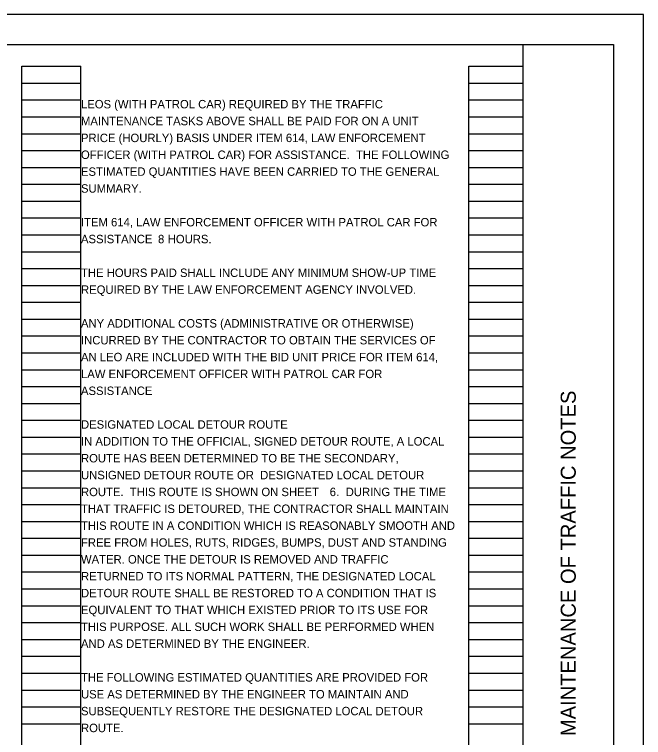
# Model space of a CAD drawing. Extents: x -8.6 to 34, y 0 to 22.
# Drawn here: x 23.56 to 34, y 9.99 to 22 of the extents above; entities that cross this region are included whole.
import ezdxf

# ---------------------------------------------------------------- set-up
doc = ezdxf.new("R2010")
doc.units = 0
for name, color, linetype in [('SC_Scratch1', 7, 'Continuous'), ('SH_Border', 7, 'Continuous'), ('SH_Cut_Line', 7, 'Continuous'), ('SH_Data', 7, 'Continuous'), ('SH_Text', 7, 'Continuous')]:
    doc.layers.add(name, color=color, linetype=linetype)

msp = doc.modelspace()

# ---------------------------------------------------------------- linework, layer by layer
at = {"layer": 'SC_Scratch1'}
for p, q in [((23.68, 0.98), (23.68, 21.14)), ((23.68, 21.14), (24.66, 21.14)), ((24.66, 0.98), (24.66, 21.14)), ((31.1, 0.98), (31.1, 21.14)), ((31.1, 21.14), (32, 21.14)), ((32, 0.98), (32, 21.14)), ((23.68, 20.86), (24.66, 20.86)), ((31.1, 20.86), (32, 20.86)), ((23.68, 20.58), (24.66, 20.58)), ((31.1, 20.58), (32, 20.58)), ((23.68, 20.3), (24.66, 20.3)), ((31.1, 20.3), (32, 20.3)), ((23.68, 20.02), (24.66, 20.02)), ((31.1, 20.02), (32, 20.02)), ((23.68, 19.74), (24.66, 19.74)), ((31.1, 19.74), (32, 19.74)), ((23.68, 19.46), (24.66, 19.46)), ((31.1, 19.46), (32, 19.46)), ((23.68, 19.18), (24.66, 19.18)), ((31.1, 19.18), (32, 19.18)), ((23.68, 18.9), (24.66, 18.9)), ((31.1, 18.9), (32, 18.9)), ((23.68, 18.62), (24.66, 18.62)), ((31.1, 18.62), (32, 18.62)), ((23.68, 18.34), (24.66, 18.34)), ((31.1, 18.34), (32, 18.34)), ((23.68, 18.06), (24.66, 18.06)), ((31.1, 18.06), (32, 18.06)), ((23.68, 17.78), (24.66, 17.78)), ((31.1, 17.78), (32, 17.78)), ((23.68, 17.5), (24.66, 17.5)), ((31.1, 17.5), (32, 17.5)), ((23.68, 17.22), (24.66, 17.22)), ((31.1, 17.22), (32, 17.22)), ((23.68, 16.94), (24.66, 16.94)), ((31.1, 16.94), (32, 16.94)), ((23.68, 16.66), (24.66, 16.66)), ((31.1, 16.66), (32, 16.66)), ((23.68, 16.38), (24.66, 16.38)), ((31.1, 16.38), (32, 16.38)), ((23.68, 16.1), (24.66, 16.1)), ((31.1, 16.1), (32, 16.1)), ((23.68, 15.82), (24.66, 15.82)), ((31.1, 15.82), (32, 15.82)), ((23.68, 15.54), (24.66, 15.54)), ((31.1, 15.54), (32, 15.54)), ((23.68, 15.26), (24.66, 15.26)), ((31.1, 15.26), (32, 15.26)), ((23.68, 14.98), (24.66, 14.98)), ((31.1, 14.98), (32, 14.98)), ((23.68, 14.7), (24.66, 14.7)), ((31.1, 14.7), (32, 14.7)), ((23.68, 14.42), (24.66, 14.42)), ((31.1, 14.42), (32, 14.42)), ((23.68, 14.14), (24.66, 14.14)), ((31.1, 14.14), (32, 14.14)), ((23.68, 13.86), (24.66, 13.86)), ((31.1, 13.86), (32, 13.86)), ((23.68, 13.58), (24.66, 13.58)), ((31.1, 13.58), (32, 13.58)), ((23.68, 13.3), (24.66, 13.3)), ((31.1, 13.3), (32, 13.3)), ((23.68, 13.02), (24.66, 13.02)), ((31.1, 13.02), (32, 13.02)), ((23.68, 12.74), (24.66, 12.74)), ((31.1, 12.74), (32, 12.74)), ((23.68, 12.46), (24.66, 12.46)), ((31.1, 12.46), (32, 12.46)), ((23.68, 12.18), (24.66, 12.18)), ((31.1, 12.18), (32, 12.18)), ((23.68, 11.9), (24.66, 11.9)), ((31.1, 11.9), (32, 11.9)), ((23.68, 11.62), (24.66, 11.62)), ((31.1, 11.62), (32, 11.62)), ((23.68, 11.34), (24.66, 11.34)), ((31.1, 11.34), (32, 11.34)), ((23.68, 11.06), (24.66, 11.06)), ((31.1, 11.06), (32, 11.06)), ((23.68, 10.78), (24.66, 10.78)), ((31.1, 10.78), (32, 10.78)), ((23.68, 10.5), (24.66, 10.5)), ((31.1, 10.5), (32, 10.5)), ((23.68, 10.22), (24.66, 10.22)), ((31.1, 10.22), (32, 10.22))]:
    msp.add_line(p, q, dxfattribs=at)
at = {"layer": 'SH_Border'}
msp.add_line((32, 0.5), (32, 21.5), dxfattribs=at)
msp.add_lwpolyline([(1.5, 21.5), (33.5, 21.5), (33.5, 0.5), (1.5, 0.5)], close=True, dxfattribs=at)
at = {"layer": 'SH_Cut_Line'}
msp.add_lwpolyline([(0, 0), (34, 0), (34, 22), (0, 22)], close=True, dxfattribs=at)

# ---------------------------------------------------------------- texts
at = {"layer": 'SH_Data'}
msp.add_text('MAINTENANCE OF TRAFFIC NOTES', height=0.25, rotation=90, dxfattribs=at).set_placement((32.875, 10.014))
at = {"layer": 'SH_Text'}
for s, p in [('LEOS (WITH PATROL CAR) REQUIRED BY THE TRAFFIC ', (24.66, 20.44)), ('MAINTENANCE TASKS ABOVE SHALL BE PAID FOR ON A UNIT ', (24.66, 20.16)), ('PRICE (HOURLY) BASIS UNDER ITEM 614, LAW ENFORCEMENT ', (24.66, 19.88)), ('OFFICER (WITH PATROL CAR) FOR ASSISTANCE.  THE FOLLOWING ', (24.66, 19.6)), ('ESTIMATED QUANTITIES HAVE BEEN CARRIED TO THE GENERAL ', (24.66, 19.32)), ('SUMMARY.', (24.66, 19.04)), ('ITEM 614, LAW ENFORCEMENT OFFICER WITH PATROL CAR FOR ', (24.66, 18.48)), ('ASSISTANCE ', (24.66, 18.2)), ('8', (25.939, 18.2)), (' HOURS.', (26.048, 18.2)), ('THE HOURS PAID SHALL INCLUDE ANY MINIMUM SHOW-UP TIME ', (24.66, 17.64)), ('REQUIRED BY THE LAW ENFORCEMENT AGENCY INVOLVED.', (24.66, 17.36)), ('ANY ADDITIONAL COSTS (ADMINISTRATIVE OR OTHERWISE) ', (24.66, 16.8)), ('INCURRED BY THE CONTRACTOR TO OBTAIN THE SERVICES OF ', (24.66, 16.52)), ('AN LEO ARE INCLUDED WITH THE BID UNIT PRICE FOR ITEM 614, ', (24.66, 16.24)), ('LAW ENFORCEMENT OFFICER WITH PATROL CAR FOR ', (24.66, 15.96)), ('ASSISTANCE', (24.66, 15.68)), ('DESIGNATED LOCAL DETOUR ROUTE', (24.66, 15.12)), ('IN ADDITION TO THE OFFICIAL, SIGNED DETOUR ROUTE, A LOCAL ', (24.66, 14.84)), ('ROUTE HAS BEEN DETERMINED TO BE THE SECONDARY, ', (24.66, 14.56)), ('UNSIGNED DETOUR ROUTE OR  DESIGNATED LOCAL DETOUR ', (24.66, 14.28)), ('ROUTE.  THIS ROUTE IS SHOWN ON SHEET ', (24.66, 14)), ('6', (28.79, 14)), ('.  DURING THE TIME ', (28.899, 14)), ('THAT TRAFFIC IS DETOURED, THE CONTRACTOR SHALL MAINTAIN ', (24.66, 13.72)), ('THIS ROUTE IN A CONDITION WHICH IS REASONABLY SMOOTH AND ', (24.66, 13.44)), ('FREE FROM HOLES, RUTS, RIDGES, BUMPS, DUST AND STANDING ', (24.66, 13.16)), ('WATER. ONCE THE DETOUR IS REMOVED AND TRAFFIC ', (24.66, 12.88)), ('RETURNED TO ITS NORMAL PATTERN, THE DESIGNATED LOCAL ', (24.66, 12.6)), ('DETOUR ROUTE SHALL BE RESTORED TO A CONDITION THAT IS ', (24.66, 12.32)), ('EQUIVALENT TO THAT WHICH EXISTED PRIOR TO ITS USE FOR ', (24.66, 12.04)), ('THIS PURPOSE. ALL SUCH WORK SHALL BE PERFORMED WHEN ', (24.66, 11.76)), ('AND AS DETERMINED BY THE ENGINEER.', (24.66, 11.48)), ('THE FOLLOWING ESTIMATED QUANTITIES ARE PROVIDED FOR ', (24.66, 10.92)), ('USE AS DETERMINED BY THE ENGINEER TO MAINTAIN AND ', (24.66, 10.64)), ('SUBSEQUENTLY RESTORE THE DESIGNATED LOCAL DETOUR ', (24.66, 10.36)), ('ROUTE.', (24.66, 10.08))]:
    msp.add_text(s, height=0.14, dxfattribs=at).set_placement(p)

doc.saveas('drawing.dxf')
